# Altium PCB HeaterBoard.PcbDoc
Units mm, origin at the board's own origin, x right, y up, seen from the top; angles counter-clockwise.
Board outline 93.5 x 57 mm, 2 copper layers (Top Layer, Bottom Layer), stack 1.586 mm thick; 92 components, 36 nets, 205 pads, 73 vias.
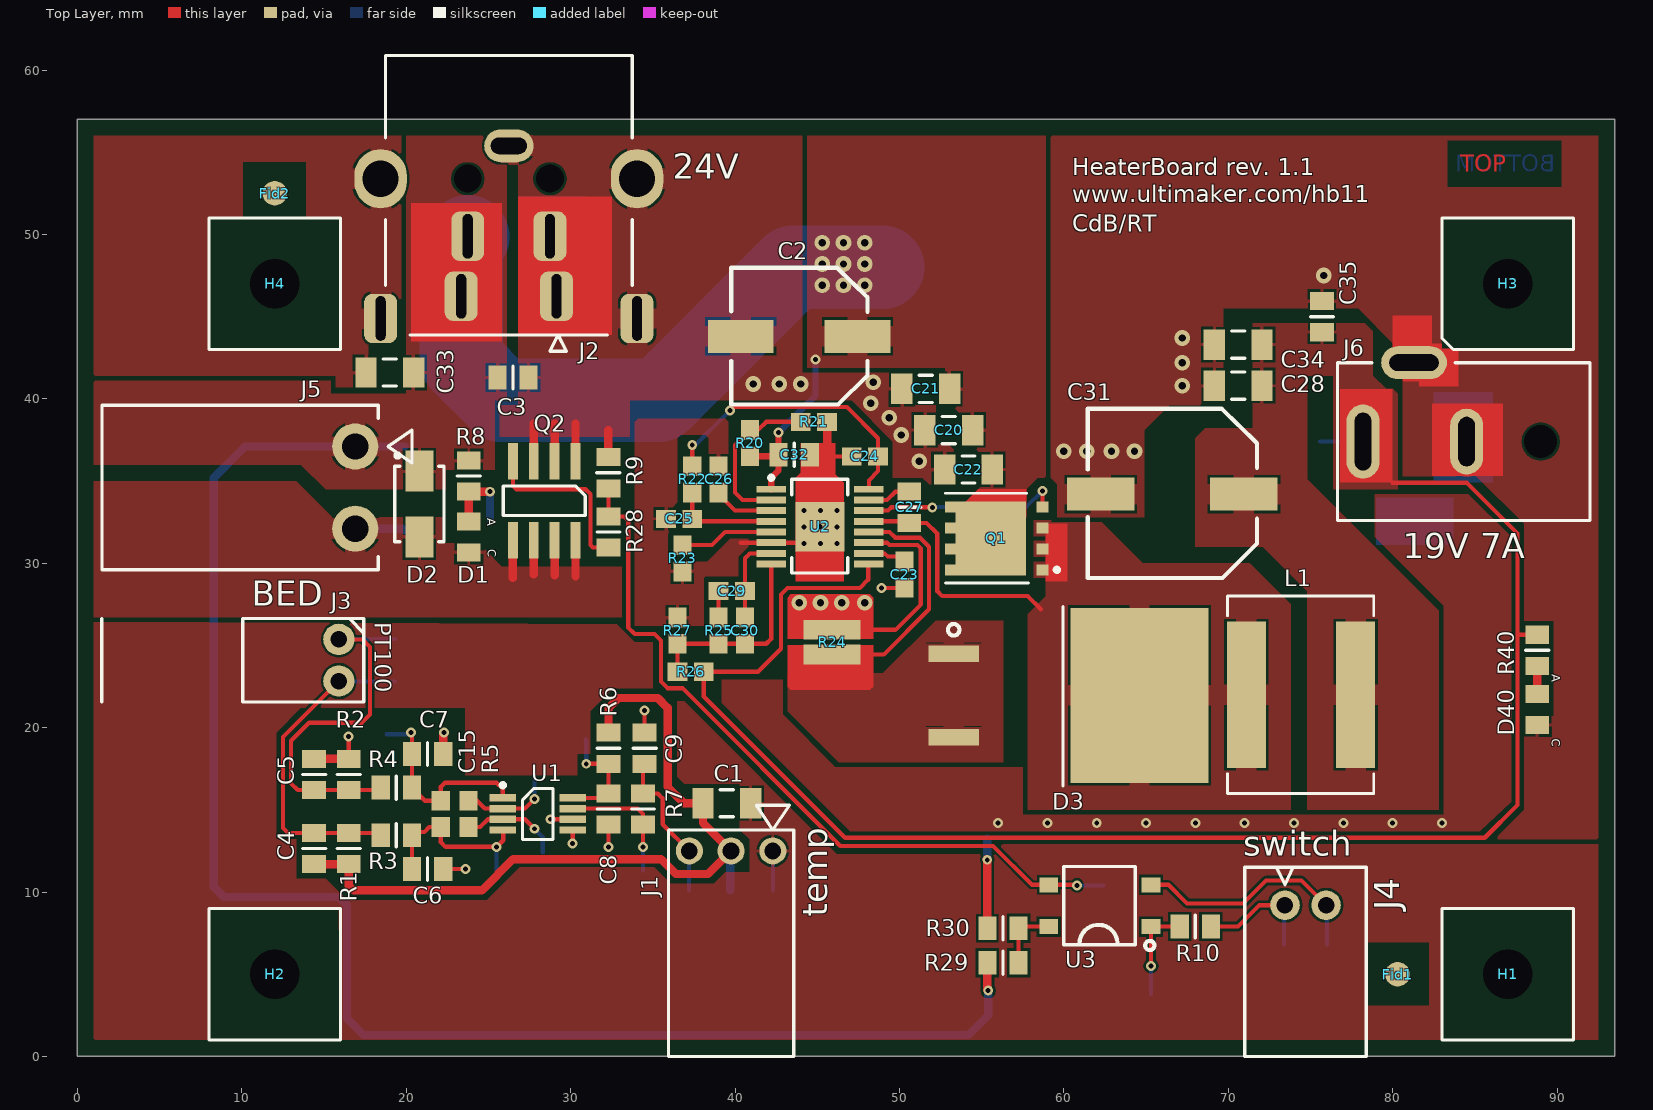
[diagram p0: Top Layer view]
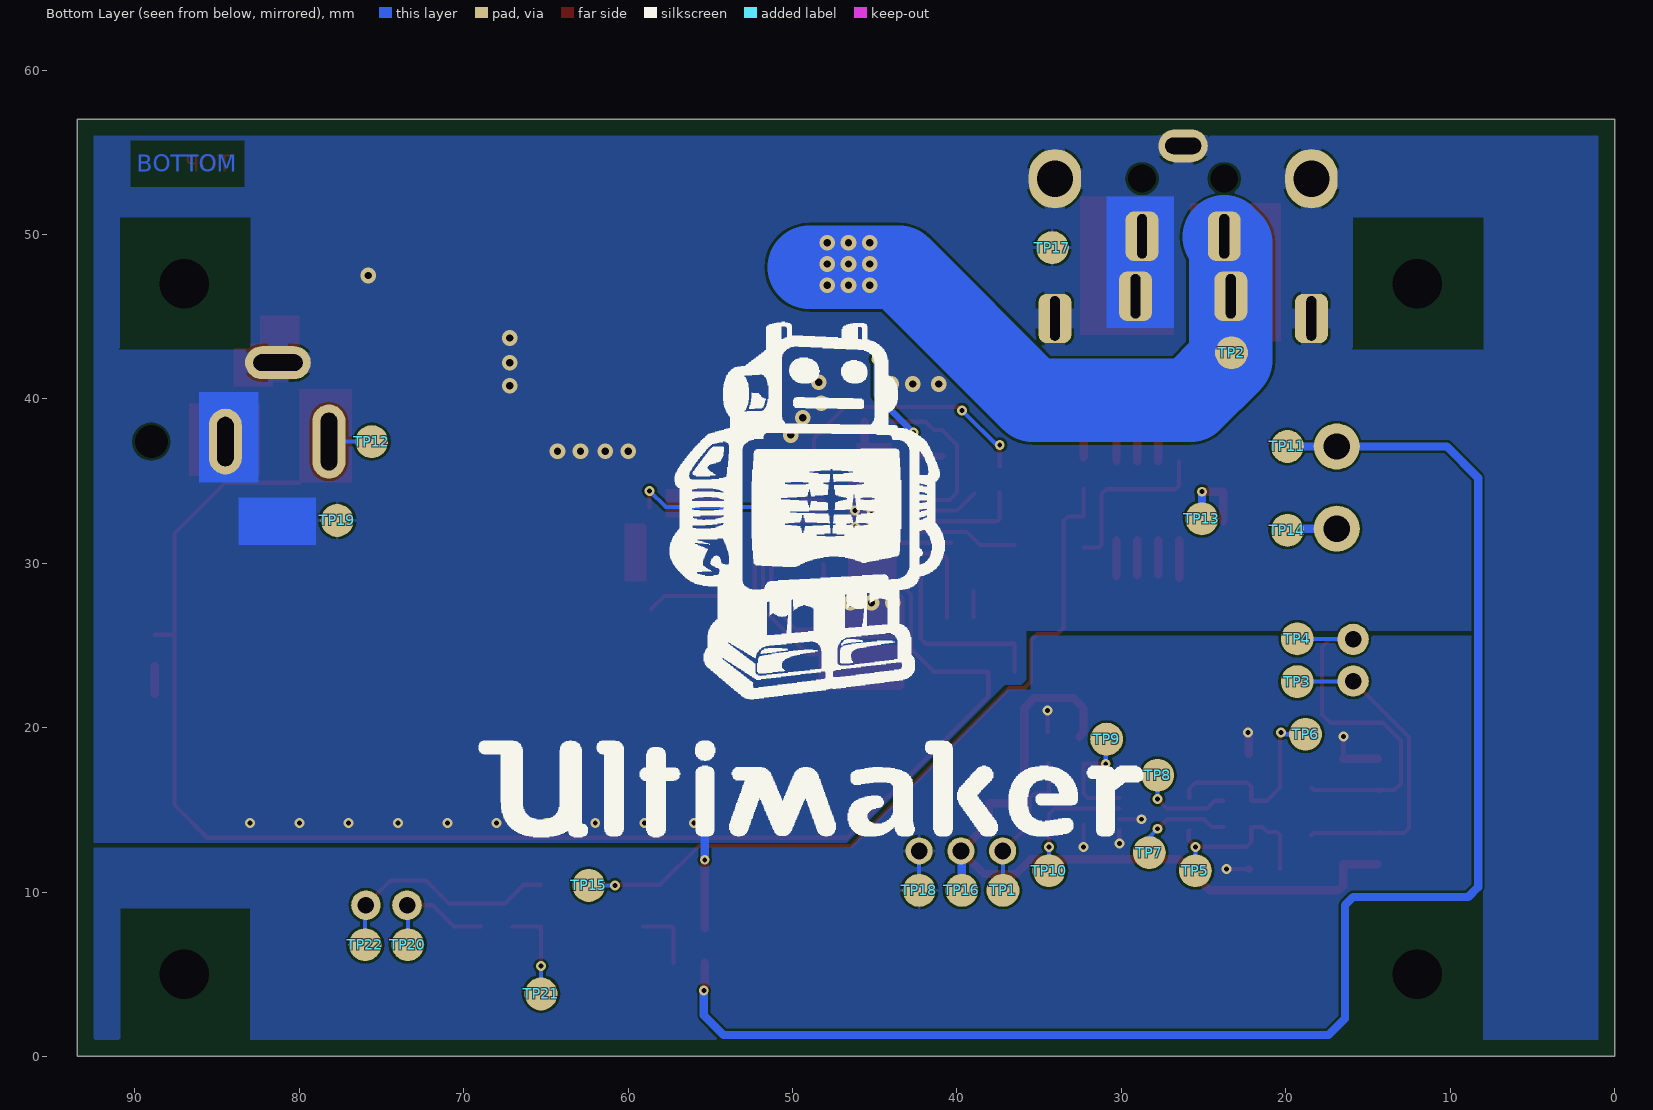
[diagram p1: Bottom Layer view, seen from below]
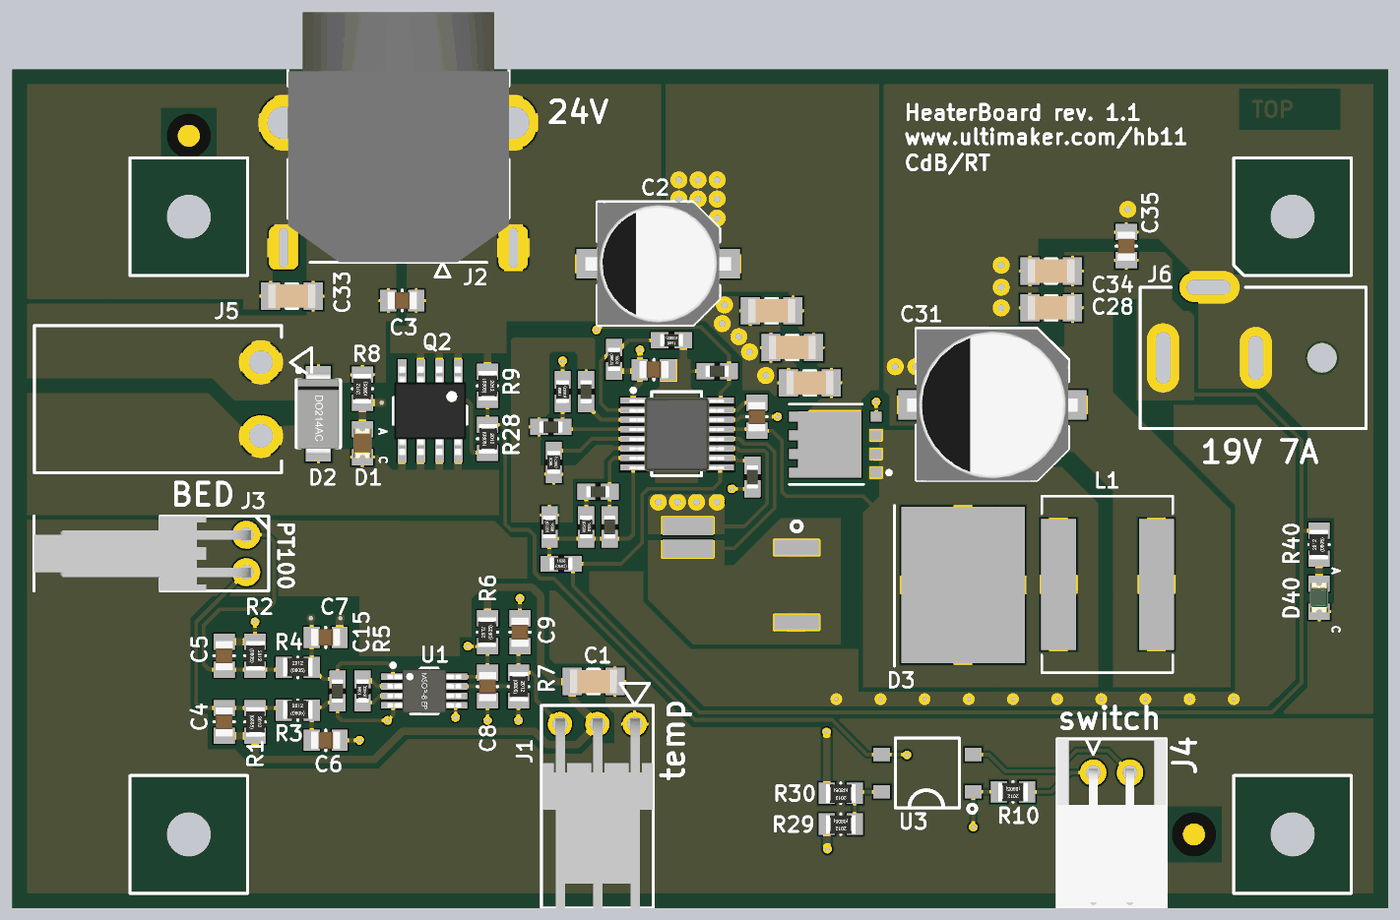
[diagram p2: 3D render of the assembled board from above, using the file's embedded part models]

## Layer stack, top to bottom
Top Layer: signal copper 0.018
Dielectric: core 1.55, FR-4, Dk 4.8
Bottom Layer: signal copper 0.018

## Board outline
0,0 0,57 93.5,57 93.5,0

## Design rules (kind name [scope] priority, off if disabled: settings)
Clearance Clearance-xPP-xTP-xTT [All] p1: gap=0.15
ComponentClearance [All] p1: gap=0.25 collisioncheckmode=3 verticalgap=0.25 showdistances=FALSE
DiffPairsRouting [All] p1: maxlimit=0.25 minlimit=0.25 mostfreqgap=0.25 maxuncoupledlength=12.5
Height [All] p1: minheight=0 maxheight=25 prefheight=12.5
HoleSize HoleSize-PTH [All] p1: absolutevalues=TRUE maxlimit=4 minlimit=0.25 maxpercent=80.000 minpercent=20.000
HoleToHoleClearance [All] p1: gap=0.15 allowstackedmicrovias=TRUE
MinimumAnnularRing "Minimum IAR  >0.45mm" [((ObjectKind = 'Pad') OR (ObjectKind = 'Via')) And (Layer = 'MultiLayer') And (HoleDiameter > AsMM(0.45))] p1: minimumring=0.15 // minimum inner annular ring for pads > 0.45mm finished hole size
MinimumAnnularRing "Minimum IAR <=0.45mm" [((ObjectKind = 'Pad') OR (ObjectKind = 'Via')) And (Layer = 'MultiLayer') And (HoleDiameter <= AsMM(0.45))] p2: minimumring=0.15 // minimum inner annular ring for pads <= 0.45mm finished hole size
MinimumSolderMaskSliver [All] p1: minsoldermaskwidth=0.1
PlaneClearance PlaneClearance-IPI [All] p1: clearance=0.4
PlaneConnect [All] p1: planeconnectstyle=Relief reliefexpansion=0.4 reliefentries=4 reliefconductorwidth=0.2 reliefairgap=0.2
PolygonConnect "PolygonConnect 50mill" [(InComponent('J2'))or (InComponent('C2'))or (InComponent('Q1'))or (InComponent('L1'))or (InComponent('R24'))     or (InComponent('C31'))  or (InComponent('J6'))or (InComponent('D3'))  or (InComponent('J5'))] p1: connectstyle=Relief reliefconductorwidth=1.27 reliefentries=4 polygonreliefangle="90 Angle"
PolygonConnect "PolygonConnect via" [IsVia] p2: connectstyle=Direct reliefconductorwidth=0.254 reliefentries=4 polygonreliefangle="90 Angle"
PolygonConnect PolygonConnect-xTW [All] p3: connectstyle=Relief reliefconductorwidth=0.2 reliefentries=4 polygonreliefangle="90 Angle"
RoomDefinition HeaterBoard [InComponentClass('HeaterBoard')] p1 off: confinementstyle=ConfineIn formatcopy=TRUE lockcomponents=FALSE outline 94.5,-8 107,-8 107,-3.7 94.5,-3.7
RoutingCorners [All] p1: cornerstyle=45-Degree minsetback=2.5 maxsetback=2.5
RoutingVias "RoutingVias > 0.45mm" [(ObjectKind = 'Via') And (HoleDiameter > AsMM(0.45))] p1: holewidth=0.5 width=1 viastyle="Through Hole" minholewidth=0.45 minwidth=0.95 maxholewidth=0.9 maxwidth=1.4 // finishet hole size > 0.45mm
RoutingVias "RoutingVias <= 0.45mm" [(ObjectKind = 'Via') And (HoleDiameter <= AsMM(0.45))] p2: holewidth=0.3 width=0.8 viastyle="Through Hole" minholewidth=0.25 minwidth=0.7 maxholewidth=0.5 maxwidth=1 // finishet hole size <= 0.45mm
SilkToSilkClearance [All] p1: silktosilkclearance=0.2
SilkscreenOverComponentPads [All] p1: minsilkscreentomaskgap=0.2
SolderMaskExpansion [All] p1: expansion=0.1
Width Width-xTW [All] p1: maxlimit=6.35 minlimit=0.15 preferedwidth=0.2 minimp=50.000000 maximp=50.000000 favimp=50.000000
17 further rules are at their usual default settings.

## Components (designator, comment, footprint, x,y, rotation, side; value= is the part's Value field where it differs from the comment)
C1 "10uF" "C1206 (3216)" 39.5,15.4 r180 top
C2 "150uF/35V" "ELCO Case F" 43.9,43.8 r0 top
C3 "100nF" "C0805 (2012)" 26.5,41.3 r0 top
C4 "100nF" "C0805 (2012)" 14.4,12.65 r90 top
C5 "100nF" "C0805 (2012)" 14.4,17.15 r90 top
C6 "100nF" "C0805 (2012)" 21.3,11.4 r180 top
C7 "100nF" "C0805 (2012)" 21.3,18.4 r0 top
C8 "100nF" "C0805 (2012)" 32.3,15.05 r270 top
C9 "10nF" "C0805 (2012)" 34.5,18.75 r270 top
C15 "1uF" "C0603 (1608)" 22.1,14.75 r270 top
C20 "4.7uF" "C1206 (3216)" 53,38.1 r0 top
C21 "4.7uF" "C1206 (3216)" 51.6,40.6 r0 top
C22 "4.7uF" "C1206 (3216)" 54.2,35.7 r0 top
C23 "2,2uF" "C0603 (1608)" 50.3,29.3 r90 top
C24 "680nF" "C0603 (1608)" 47.9,36.5 r0 top
C25 "680pF" "C0603 (1608)" 36.6,32.7 r0 top
C26 "10nF" "C0603 (1608)" 39,35.1 r270 top
C27 "33nF" "C0805 (2012)" 50.6,33.4 r90 top
C28 "4.7uF" "C1206 (3216)" 70.6,40.8 r0 top
C29 "1.5nF" "C0603 (1608)" 39.8,28.3 r180 top
C30 "100pF" "C0603 (1608)" 40.6,25.9 r270 top
C31 "330uF/35v" "ELCO CASE G" 66.6,34.2 r0 top
C32 "100nF" "C0805 (2012)" 43.6,36.6 r0 top
C33 "4.7uF" "C1206 (3216)" 19,41.6 r0 top
C34 "4.7uF" "C1206 (3216)" 70.6,43.3 r0 top
C35 "100nF" "C0805 (2012)" 75.7,45 r90 top
D1 "Red" LED0805-RED 23.8,31.6 r270 top
D2 "S1G" "DIODE DO214AC (SMA)" 20.8,33.6 r90 top
D3 "Diode Dual Schottky MBRB1545 45V 15A" "DIODE D2PAK(Case 418B)" 53.3,24.5 r180 top
D40 "Green" LED0805-GREEN 88.8,21.1 r270 top
Fid1 "Fiducial" "Fiducial 1,5mm" 80.3,5 r0 top
Fid2 "Fiducial" "Fiducial 1,5mm" 12,52.5 r90 top
H1 "3mm" "Mounting Hole 3mm NPTH" 87,5 r0 top
H2 "3mm" "Mounting Hole 3mm NPTH" 12,5 r0 top
H3 "3mm" "Mounting Hole 3mm NPTH" 87,47 r0 top
H4 "3mm" "Mounting Hole 3mm NPTH" 12,47 r0 top
J1 "22-05-3031" "HEADER 3P RIGHT ANGLE" 42.3,12.5 r180 top
J2 "KPJX-4S-S" "Con KPJX-4S-S" 26.242,53.388 r0 top
J3 "22-05-7028" "HEADER 2P RIGHT ANGLE" 15.9,24.1 r270 top
J4 "S2B-XH-A (LF)(SN)" "CON S2B-XH-A (LF)(SN)" 74.7,9.2 r0 top
J5 "2092-1372" "Con 2092-1372" 16.9,37.1 r270 top
J6 "487-836" "CON DC POWER SOCKET" 78.2,37.4 r180 top
L1 "10uH" "Inductor XAL1010-103MEB" 71.1,22 r0 top
Q1 "CSD18501Q5A" "IC SON5X6" 58.7,29.6 r0 top
Q2 "IRF8736PBF" "IC SOIC-8" 28.395,33.8 r270 top (schematic designator Q?)
R1 "2.2K" "R0805 (2012)" 16.5,12.65 r270 top
R2 "2.2K" "R0805 (2012)" 16.5,17.15 r270 top
R3 "10K" "R0805 (2012)" 19.4,13.45 r0 top
R4 "10K" "R0805 (2012)" 19.4,16.35 r0 top
R5 "5.49K" "R0603 (1608)" 23.8,14.75 r90 top
R6 "100E" "R0805 (2012)" 32.3,18.75 r90 top
R7 "100E" "R0805 (2012)" 34.4,15.05 r270 top
R8 "2.2K" "R0805 (2012)" 23.8,35.3 r90 top
R9 "1K" "R0805 (2012)" 32.295,35.5 r270 top
R10 "2.2K" "R0805 (2012)" 68,7.9 r180 top (schematic designator R?)
R20 "49.9K" "R0603 (1608)" 40.9,37.3 r270 top
R21 "3.48K" "R0603 (1608)" 44.8,38.6 r180 top
R22 "97.6K" "R0603 (1608)" 37.4,35.1 r90 top
R23 "28K" "R0603 (1608)" 36.8,30.3 r90 top
R24 "0E007" R1632X06N 45.9,25.2 r270 top
R25 "90.9K" "R0603 (1608)" 39,25.9 r270 top
R26 "28K" "R0603 (1608)" 37.3,23.4 r0 top
R27 "1.91K" "R0603 (1608)" 36.5,25.9 r270 top
R28 "100E" "R0805 (2012)" 32.3,31.9 r270 top
R29 "1K" "R0805 (2012)" 56.3,5.7 r180 top
R30 "1K" "R0805 (2012)" 56.3,7.8 r180 top
R40 "2.2K" "R0805 (2012)" 88.8,24.7 r90 top
TP1 "2mm" "TESTPOINT 2mm" 37.2,10.1 r90 bottom
TP2 "2mm" "TESTPOINT 2mm" 23.3,42.8 r270 bottom
TP3 "2mm" "TESTPOINT 2mm" 19.3,22.8 r270 bottom
TP4 "2mm" "TESTPOINT 2mm" 19.3,25.4 r270 bottom
TP5 "2mm" "TESTPOINT 2mm" 25.5,11.3 r270 bottom
TP6 "2mm" "TESTPOINT 2mm" 18.8,19.6 r270 bottom
TP7 "2mm" "TESTPOINT 2mm" 28.3,12.4 r270 bottom
TP8 "2mm" "TESTPOINT 2mm" 27.8,17.1 r270 bottom
TP9 "2mm" "TESTPOINT 2mm" 30.9,19.3 r270 bottom
TP10 "2mm" "TESTPOINT 2mm" 34.4,11.3 r270 bottom
TP11 "2mm" "TESTPOINT 2mm" 19.9,37.1 r270 bottom
TP12 "2mm" "TESTPOINT 2mm" 75.6,37.4 r270 bottom
TP13 "2mm" "TESTPOINT 2mm" 25.1,32.7 r270 bottom
TP14 "2mm" "TESTPOINT 2mm" 19.9,32 r270 bottom
TP15 "2mm" "TESTPOINT 2mm" 62.4,10.4 r270 bottom
TP16 "2mm" "TESTPOINT 2mm" 39.7,10.1 r180 bottom
TP17 "2mm" "TESTPOINT 2mm" 34.2,49.2 r270 bottom
TP18 "2mm" "TESTPOINT 2mm" 42.3,10.1 r270 bottom
TP19 "2mm" "TESTPOINT 2mm" 77.7,32.6 r270 bottom
TP20 "2mm" "TESTPOINT 2mm" 73.4,6.8 r0 bottom
TP21 "2mm" "TESTPOINT 2mm" 65.3,3.8 r0 bottom
TP22 "2mm" "TESTPOINT 2mm" 76,6.8 r0 bottom
U1 "INA826" "IC MSOP8" 28,14.75 r0 top
U2 "LM25088MH-1" "IC HTSSOP-16" 42.2,34.5 r0 top
U3 "SFH690BT" "IC SOP-4" 65.3,7.9 r180 top

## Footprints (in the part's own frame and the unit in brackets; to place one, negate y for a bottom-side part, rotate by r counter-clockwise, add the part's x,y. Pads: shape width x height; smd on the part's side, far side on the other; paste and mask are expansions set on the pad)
"C0603 (1608)" [mm] "Chip Capacitor, 2-Leads, Body 1.6x0.8mm, IPC Medium Density"
  rect 1.2x1.1 smd: 1(-0.8,0) 2(0.8,0)
  body extent -0.8,-0.4 0.8,0.4, height 0.9
"C0805 (2012)" [mm] "hip Capacitor, 2-Leads, Body 2,0x1.25mm, IPC Medium Density"
  rect 1.1x1.45 smd: 1(-0.95,0) 2(0.95,0)
  silkscreen extent 0,-0.7 0,0.7, body extent -1,-0.6 1,0.6, height 1.19
"C1206 (3216)" [mm] "Chip Capacitor, 2-Leads, Body 3.2x1.6mm, IPC Medium Density"
  rect 1.3x1.85 smd: 1(-1.45,0) 2(1.45,0)
  silkscreen extent -0.4,-0.82 0.4,0.82, body extent -1.6,-0.8 1.6,0.8, height 0.77
"Con 2092-1372" [mm] "Connector 2092-1372 2p therm Block r.a."
  round 2.8 hole 1.6: 1(0,0) 2(5,0)
  silkscreen extent -2.5,-15.4 7.5,3.45, body extent -2.5,-15.4 7.5,1.4, height 13.4
"CON DC POWER SOCKET" [mm]
  round 0 hole 2: 0(-10.8,0)
  oval 2x4.5 hole 1 slot 3.5 at 90 deg: 1(0,0)
  oval 2x4 hole 1 slot 3 at 90 deg: 2(-6.3,0)
  oval 4x2 hole 1 slot 3 at 0 deg: 3(-3.1,-4.8)
  silkscreen extent -13.8,-4.8 1.55,4.8
"Con KPJX-4S-S" [mm]
  round 0 hole 1.7 unplated: 0(-2.5,0) 0(2.5,0)
  rrect50% 2x3 hole 0.6 slot 2.7 at 90 deg: 1(2.9,-7.15) 2(-2.9,-7.15) 3(2.5,-3.5) 4(-2.5,-3.5) 5(-7.8,-8.5) 5(7.8,-8.5)
  oval 3.2x3.6 hole 2.2: 5(-7.8,0) 5(7.8,0)
  oval 3x2 hole 1 slot 2.2 at 0 deg: 5(0,2)
  silkscreen extent -7.5,-10.5 7.5,7.5, body extent -7.5,-9.5 7.5,7.5, height 15
"CON S2B-XH-A (LF)(SN)" [mm]
  round 1.8 hole 1: 1(-1.25,0) 2(1.25,0)
  silkscreen extent -3.7,-9.2 3.7,2.3, body extent -3.7,-9.2 3.7,2.3, height 6.1
"DIODE D2PAK(Case 418B)" [mm]
  rect 3.05x1.016 smd: 1(0,0) 3(0,5.08)
  rect 8.38x10.66 smd: 4(-11.305,2.54)
  silkscreen extent -6.65,-2.85 0.35,8.05
"DIODE DO214AC (SMA)" [mm] "Molded Diode, 2-Leads, Body 4.3x2.6mm, IPC Medium Density"
  rect 2.5x1.7 smd: 1(-2,0) 2(2,0)
  silkscreen extent -2.3,-1.5 3.07,1.5, body extent -2.74,-1.4 2.74,1.4, height 2.3
"ELCO Case F" [mm] "Panasonic Elco 8x10,5mm (dxh)"
  rect 4x2 smd: 1(3.55,0) 2(-3.55,0)
  silkscreen extent -4.13,-4.15 4.15,4.18, body extent -4.95,-4.15 4.95,4.15, height 10.21
"ELCO CASE G" [mm] "Panasonic Elco 10x10,5mm (dxh)"
  rect 4.1x2 smd: 1(4.35,0) 2(-4.35,0)
  silkscreen extent -5.15,-5.1 5.15,5.2, body extent -5.8,-5.15 5.8,5.15, height 10.21
"Fiducial 1,5mm" [mm] "Fiducial 1,5mm"
  round 1.5 smd paste-3 mask+0.75: ""(0,0)
"HEADER 2P RIGHT ANGLE" [mm]
  round 1.9 hole 1: 1(-1.27,0) 2(1.27,0)
  silkscreen extent -2.54,-14.42 2.54,1.52, body extent -2.54,-14.42 2.54,0.32, height 5.87
"HEADER 3P RIGHT ANGLE" [mm]
  round 1.65 hole 1.02: 1(0,0) 2(2.54,0) 3(5.08,0)
  silkscreen extent -1.27,-2.77 6.35,12.5, body extent -1.23,-0.4 6.23,12.53, height 6.38
"IC HTSSOP-16" [mm] "PWP0016A"
  rect 3x3 smd: 0(2.97,-2.275)
  rect 1.78x0.42 smd: 1(0,0) 2(0,-0.65) 3(0,-1.3) 4(0,-1.95) 5(0,-2.6) 6(0,-3.25) 7(0,-3.9) 8(0,-4.55) 9(5.94,-4.55) 10(5.94,-3.9) 11(5.94,-3.25) 12(5.94,-2.6) 13(5.94,-1.95) 14(5.94,-1.3) 15(5.94,-0.65) 16(5.94,0)
  silkscreen extent -0.12,-5.1 4.65,0.82, body extent -0.25,-4.8 6.17,0.2, height 0.99
"IC MSOP8" [mm] "TSOP, 8-Leads, Body 3.1x3.1mm (max), Pitch 0.65mm, IPC Medium Density"
  rect 1.6x0.45 smd: 1(-2.125,0.975) 2(-2.125,0.325) 3(-2.125,-0.325) 4(-2.125,-0.975) 5(2.125,-0.975) 6(2.125,-0.325) 7(2.125,0.325) 8(2.125,0.975)
  silkscreen extent -2.25,-1.55 0.92,1.87, body extent -2.5,-1.5 2.5,1.5, height 1.09
"IC SOIC-8" [mm] "SOIC, 8-Leads, Body 5,0x4,0mm (max), Pitch 1,27mm, IPC Medium Density"
  rect 2.2x0.6 smd: 1(-2.4,1.905) 2(-2.4,0.635) 3(-2.4,-0.635) 4(-2.4,-1.905) 5(2.4,-1.905) 6(2.4,-0.635) 7(2.4,0.635) 8(2.4,1.905)
  silkscreen extent -0.9,-2.5 0.9,2.5, body extent -3,-2.45 3,2.45, height 1.75
"IC SON5X6" [mm] "IC SON5x6"
  rect 4.3x4.5 smd: 0(-3.15,1.905)
  rect 0.75x0.67 smd: 1(0,0) 2(0,1.27) 3(0,2.54) 4(0,3.81)
  rect 0.65x0.67 smd: 5(-5.6,3.81) 6(-5.6,2.54) 7(-5.6,1.27) 8(-5.6,0)
  silkscreen extent -5.9,-0.8 1,4.65
"IC SOP-4" [mm]
  rect 1.14x0.91 smd: 1(0,0) 2(0,-2.54) 3(6.22,-2.54) 4(6.22,0)
  silkscreen extent -0.21,-3.65 5.3,1.43
"Inductor XAL1010-103MEB" [mm] "Inductor XAL1010-103MEB"
  rect 2.38x8.91 smd paste+0: 1(0,0) 2(6.65,0)
  silkscreen extent -1.15,-6 7.75,6
LED0805-GREEN [mm]
  rect 1.1x1.45 smd: 1(-0.95,0) 2(0.95,0)
  body extent -1.01,-0.62 1.01,0.63, height 1.1
LED0805-RED [mm]
  rect 1.1x1.45 smd: 1(-0.95,0) 2(0.95,0)
  body extent -1.01,-0.62 1.01,0.63, height 1.1
"Mounting Hole 3mm NPTH" [mm] "Mounting Hole 3mm NPTH"
  round 0 hole 3 unplated: 0(0,0)
"R0603 (1608)" [mm] "hip Resistor, 2-Leads, Body 1.55x0.85mm, IPC Medium Density"
  rect 1.2x1.1 smd: 1(-0.8,0) 2(0.8,0)
  body extent -0.77,-0.42 0.78,0.43, height 0.45
"R0805 (2012)" [mm] "hip Resistor, 2-Leads, Body 2,0x1.25mm, IPC Medium Density"
  rect 1.1x1.45 smd: 1(-0.95,0) 2(0.95,0)
  silkscreen extent 0,-0.7 0,0.7, body extent -1,-0.6 1,0.65, height 0.44
R1632X06N [mm] "Chip Resistor, 2-Leads, Body 1.6x3.2mm, IPC Medium Density"
  rect 1.2x3.45 smd: 1(-0.75,0) 2(0.75,0)
  body extent -0.9,-1.7 0.9,1.7, height 0.6
"TESTPOINT 2mm" [mm] "TESTPOINT 2mm"
  round 2 smd paste-2 mask+0: 1(0,0)

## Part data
C1: library part "Cap 10uF X7R 1206", "Cap 10uF X7R 1206  10% 25V"
C2: "Cap elco 150uF 35V case F  EEHZA1 PAN"
C3 C4 C5 C6 C7 C8 C32 C35: library part "Cap 100nF X7R 0805", "Cap 100nF X7R 0805 10% 50V"
C9: library part "Cap 10nF X7R 0805", "Cap 10nF X7R 0805 10% 50V"
C15: library part "Cap 1uF X5R 0603", "Cap 1uF X5R 0603 10% 10V"
C20 C21 C22 C28 C33 C34: library part "Cap 4.7uF 50V X7R 1206", "Cap 4.7uF X7R 1206 10% 50V"
C23: library part "Cap 2,2uF X7R 0603", "Cap 2,2uF X7R 0603 10% 6,3V"
C24: library part "Cap 680nF X7R 0603", "Cap 680nF X7R 0603 10% 16V"
C25: library part "Cap 680pF X7R 0603", "Cap 680pF NPO 0603 5% 50V"
C26: library part "Cap 10nF X7R 0603", "Cap 10nF X7R 0603 10% 50V"
C27: library part "Cap 33nF X7R 0805", "Cap 33nF X7R 0805 10% 50V"
C29: library part "Cap 1.5nF X7R 0603", "Cap 1.5nF X7R 0603 5% 50V"
C30: library part "Cap 100pF X7R 0603", "Cap 100pF X7R 0603 5% 50V"
C31: "Cap elco 330uF 35V case G UD Nichicon"
D1: "LED ROOD HSMH-C170 0805 AVAGO"
D2: library part "Diode S1G", "Diode S1G DO-214AC 400V 1A"
D3: library part "Diode MBRB1545", "MBRB1545"
D40: "LED GROEN HSMG-C170 0805 AVAGO"
H1 H2 H3 H4: "Mounting Hole 3mm NPTH"
J1: "Header 3p right angle 22-05-3031 Molex"
J2: "Connector 5p KPJX-4S-S KYCON"
J3: "Header 2p right angle 22-05-7028 Molex"
J4: "Connector S2B-XH-A (LF)(SN)  2p r.a."
J5: "Connector 2092-1372 2p therm Block r.a."
J6: "DC Power Socket 2.5mm Right Angle PCB Mount"
L1: library part "Inductor 10uH SMD", "Inductor 10uH 11A SMD"
Q1: library part "MOSFET-N CSD18501Q5A", "MOSFET-N CSD18501Q5A 40V 100A"
Q2: "MOSFET-N IRF8736PBF 30V 18A"
R1 R2 R8 R10 R40: library part "Res 2.2K 0805", "Res 2.2K 0805 1% 100mW"
R3 R4: library part "Res 10K 0805", "Res 10K 0805 1% 100mW"
R5: library part "Res 5.49K 0603", "Res 5.49K 0603 1% 63mW"
R6 R7 R28: library part "Res 100E 0805", "Res 100E 0805 1% 125mW"
R9 R29 R30: library part "Res 1K 0805", "Res 1K 0805 1% 100mW"
R20: library part "Res 49.9K 0603", "Res 49.9K 0603 1% 63mW"
R21: library part "Res 3.48K 0603", "Res 3.48K 0603 1% 63mW"
R22: library part "Res 97.6K 0603", "Res 97.6K 0603 1% 63mW"
R23 R26: library part "Res 28K 0603", "Res 28K 0603 1% 63mW"
R24: library part "Res 0E007 1632", "Res 0E007 1632 1% 1W"
R25: library part "Res 90.9K 0603", "Res 90.9K 0603 1% 63mW"
R27: library part "Res 1.91K 0603", "Res 1.91K 0603 1% 63mW"
TP1 TP2 TP3 TP4 TP5 TP6 TP7 TP8 TP9 TP10 TP11 TP12 TP13 TP14 TP15 TP16 TP17 TP18 TP19 TP20 TP21 TP22: "Testpoint, 2mm, round"
U1: library part "IC INA826", "IC OP AMP, instr, 1MHz"
U2: library part "IC LM25088MH-1", "IC DC-DC Buck Controller"
U3: library part "Opto SFH690BT", "Opto SFH690BT SOP-4"

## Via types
v1: diameter 0.6, hole 0.3, Top Layer to Bottom Layer, tented bottom, 40 vias
v2: diameter 0.95, hole 0.45, Top Layer to Bottom Layer, 29 vias
v3: diameter 0.6, hole 0.3, Top Layer to Bottom Layer, tented both sides, 4 vias

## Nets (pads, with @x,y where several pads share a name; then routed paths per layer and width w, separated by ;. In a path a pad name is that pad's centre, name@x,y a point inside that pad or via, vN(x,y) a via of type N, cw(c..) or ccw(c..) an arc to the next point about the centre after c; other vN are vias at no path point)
+5V: C1.2 C4.1 J1.2 R1.2 R6.2 TP16.1 | length 47.9
  Top Layer w0.508: C4.1 R1.2 16.5,10.4 16.8,10.1 24.6,10.1 26.5,12 35.5,12 36.4,11.1 38.36,11.1 J1.2 38.05,14.21 C1.2 36.9,15.4 35.9,16.4 35.9,21.2 35.3,21.8 32.9,21.8 32.3,21.2 R6.2 R6.2@32.55,19.45
  Bottom Layer w0.508: TP16.1 39.7,12.44 J1.2
+19V: C28.2 C31.1 C34.2 C35.1 J6.1 L1.2 R26.2 R40.2 TP12.1 U2.9 | length 99.7
  Top Layer w0.254: U2.9 48.1,29.91 48.1,29 47.6,28.5 43.2,28.5 42.8,28.1 42.8,24.8 41.4,23.4 R26.2 38.1,21.9 46.7,13.3 85.6,13.3 87.6,15.3 87.6,31.8 84.5,34.9 80,34.9 ; 87.65,25.65 R40.2
  Bottom Layer w0.254: TP12.1 J6.1
+24V: C2.1 C3.1 C20.2 C21.2 C22.2 C32.1 C33.2 D2.2 J2.2 J2.4 J5.1 Q1.0 Q1.5 Q1.6 Q1.7 Q1.8 R8.2 R20.2 R29.2 TP2.1 TP11.1 U2.1 | length 147
  Top Layer w0.381: R20.2 42.55,36.5 C32.1 ; U2.1 42.2,35.2 42.65,35.65 C32.1 ; v1(42.65,37.95) C32.1
  Top Layer w0.508: R29.2 55.35,4.05 v1(55.4,4)
  Bottom Layer w0.381: TP2.1@23.342,42.35 TP2.1@23.4,42.292 ; v1(42.65,37.95) 44.9,40.2 v1(44.9,42.4)
  Bottom Layer w0.508: TP11.1 J5.1 10.2,37.1 8.3,35.2 8.3,10.3 8.9,9.7 15.9,9.7 16.4,9.2 16.4,2.3 17.4,1.3 54.2,1.3 55.4,2.5 v1(55.4,4) ; 24.8,38.4 27.3,38.4
  Bottom Layer w5.08: J2.4@23.742,49.848 23.342,49.448 J2.2 23.342,42.35 25.792,39.9 35.4,39.9 43.5,48 49,48
  other v2: 45.3,46.9 46.6,46.9 47.9,46.9 45.3,48.2 46.6,48.2 47.9,48.2 45.3,49.5 46.6,49.5 47.9,49.5
GND: C2.2 C3.2 C20.1 C21.1 C22.1 C23.1 C24.1 C25.1 C26.1 C28.1 C31.2 C32.2 C33.1 C34.1 C35.2 D40.2 J2.1 J2.3 J2.5 J6.2 J6.3 Q2.1 Q2.2 Q2.3 R9.1 R21.1 R23.1 R24.1 R27.1 R30.2 TP17.1 TP19.1 U2.0 U2.6 U2.11 | length 37.2
  Top Layer w0.254: 40.35,31.25 U2.6 44.195,31.25 v1(45.17,32.225) ; 45.3,36.5 C24.1 ; R24.1 49.75,25.95 51.3,27.5 51.3,30.9 51.1,31.1 49.4,31.1 49.25,31.25 U2.11 ; v1(48.9,28.5) C23.1
  Top Layer w0.508: Q2.3 27.76,38.495 ; Q2.2 29.03,38.495 ; Q2.1 30.3,38.495 ; R9.1 32.295,38.095 ; 45.6,36.9 R21.1 ; v1@55.3,12 v1(55.34,11.96) 55.35,11.95 R30.2
  Bottom Layer w0.508: J2.1@28.542,45.8 J2.1@28.742,46 ; v1(55.34,11.96) 55.34,13.24
  other v1: 56,14.2 59,14.2 62,14.2 65,14.2 68,14.2 71,14.2 74,14.2 77,14.2 80,14.2 83,14.2 44.2,31.2 45.2,31.2 46.2,31.2 44.2,32.2 46.2,32.2 44.2,33.2 45.2,33.2 46.2,33.2
  other v2: 43.9,27.6 45.2,27.6 46.5,27.6 47.9,27.6 51.2,36.2 60,36.8 61.4,36.8 62.9,36.8 64.3,36.8 50.1,37.8 49.37,38.84 48.25,39.73 67.2,40.8 41.1,40.9 42.7,40.9 44,40.9 48.4,41 67.2,42.2 67.2,43.7 75.8,47.5
GND2: C1.1 C5.2 C6.1 C7.2 C8.2 C9.1 J1.1 R2.1 TP18.1 U1.5 U1.6 | length 13.4
  Top Layer w0.254: R2.1 v1(16.5,19.45) ; C6.1 v1(23.6,11.4) ; v3(28.775,14.425) U1.6 ; v1(30.125,12.95) U1.5 ; v1(32.3,12.75) C8.2 ; C9.1 v1(34.5,21.05)
  Top Layer w0.508: C5.2 R2.1 ; C7.2 22.25,19.65 v3(22.3,19.7)
  Bottom Layer w0.254: TP18.1 J1.1
NetC4_2: C4.2 J3.2 R1.1 R3.1 TP3.1 | length 20
  Top Layer w0.254: C4.2@14.31,13.65 14.38,13.58 C4.2 ; J3.2 12.5,19.43 12.5,13.9 12.8,13.6 C4.2 ; R3.1 18.3,13.6 R1.1 C4.2
  Bottom Layer w0.254: J3.2@15.93,22.8 TP3.1
NetC5_1: C5.1 J3.1 R2.2 R4.1 TP4.1 | length 23.6
  Top Layer w0.254: C5.1@14.19,16.25 14.32,16.12 C5.1 ; J3.1 17.33,25.37 17.8,24.9 17.8,20.8 17.3,20.3 14.1,20.3 13,19.2 13,16.6 13.4,16.2 C5.1 ; R4.1 18.3,16.2 R2.2 C5.1
  Bottom Layer w0.254: J3.1@15.93,25.4 TP4.1
NetC6_2: C6.2 C15.2 R3.2 TP5.1 U1.4 | length 11.1
  Top Layer w0.254: C6.2 20.35,13.35 20.3,13.4 R3.2 20.55,13.65 21.1,13.65 21.4,13.95 C15.2 22.1,13.05 22.4,12.75 v1(25.5,12.75) 25.9,13.15 25.9,13.75 U1.4
  Bottom Layer w0.254: TP5.1 v1(25.5,12.75)
NetC7_1: C7.1 C15.1 R4.2 TP6.1 U1.1 | length 12.4
  Top Layer w0.254: v3@20.35,19.65 C7.1 R4.2 21.15,15.55 C15.1 22.1,16.4 22.35,16.65 25.5,16.65 25.875,16.275 U1.1
  Bottom Layer w0.254: TP6.1 20.2,19.6 v3(20.3,19.7)
NetC8_1: C8.1 R6.1 TP9.1 U1.8 | length 7
  Top Layer w0.254: U1.8 32.025,15.725 C8.1 R6.1 v1(30.95,17.8)
  Bottom Layer w0.254: TP9.1 30.95,19.25 v1(30.95,17.8)
NetC23_2: C23.2 U2.10 | length 2.4
  Top Layer w0.254: U2.10 49.1,30.6 49.3,30.4 50,30.4 C23.2
NetC24_2: C24.2 R22.2 U2.16 | length 18
  Top Layer w0.254: R22.2 v1(37.4,37.2) ; v1(39.7,39.3) 39.9,39.5 46.8,39.5 48.7,37.6 C24.2 48.7,35.6 48.14,35.04 U2.16
  Bottom Layer w0.254: v1(37.4,37.2) 37.4,37 v1(39.7,39.3)
NetC25_2: C25.2 R22.1 U2.4 | length 6.5
  Top Layer w0.254: R22.1 C25.2 37.55,32.55 U2.4
NetC26_2: C26.2 U2.3 | length 3.7
  Top Layer w0.254: C26.2@38.95,34.25 40,33.2 U2.3
NetC27_1: C27.1 D3.4 L1.1 Q1.1 Q1.2 Q1.3 U2.13 | length 14.7
  Top Layer w0.254: U2.13 50.5,32.55 C27.1 51.65,32.45 52.3,31.8 52.3,28.3 52.6,28 57.8,28 58.6,27.2
NetC27_2: C27.2 U2.15 | length 2.7
  Top Layer w0.254: U2.15 49.25,33.85 49.75,34.35 C27.2
NetC29_1: C29.1 C30.1 U2.7 | length 5.3
  Top Layer w0.254: C30.1 C29.1 40.6,30.3 40.9,30.6 U2.7
NetC29_2: C29.2 R25.1 | length 1.6
  Top Layer w0.254: R25.1 C29.2
NetC30_2: C30.2 R25.2 R26.1 R27.2 U2.8 | length 12.1
  Top Layer w0.254: R26.1 R27.2 R25.2 C30.2 41.9,25.1 42.2,25.4 U2.8
NetD1_1: D1.1 R8.1 TP13.1 | length 4.8
  Top Layer w0.508: D1.1 R8.1 v3(25.1,34.35)
  Bottom Layer w0.508: TP13.1 v3(25.1,34.35)
NetD1_2: D1.2 D2.1 J5.2 Q2.5 Q2.6 Q2.7 Q2.8 TP14.1 | length 11.7
  Top Layer w0.508: 26.49,29.105 Q2.5 ; 27.76,29.335 Q2.6 ; 29.03,29.265 Q2.7 ; 30.3,29.205 Q2.8
  Bottom Layer w0.508: J5.2 19.8,32.1 TP14.1
NetD3_1: D3.1 D3.3 R24.2 U2.12 | length 14.9
  Top Layer w0.254: R24.2 49.05,24.45 51.8,27.2 51.8,31 51.25,31.55 49.75,31.55 49.4,31.9 U2.12
NetD40_1: D40.1 R40.1 | length 1.7
  Top Layer w0.508: D40.1 R40.1
NetJ4_1: J4.1 R10.1 TP20.1 | length 7.5
  Top Layer w0.254: R10.1 70.6,7.9 71.9,9.2 J4.1
  Bottom Layer w0.254: TP20.1 73.4,9.15 J4.1
NetJ4_2: J4.2 TP22.1 U3.2 | length 14.7
  Top Layer w0.254: U3.2 66.36,10.44 67.5,9.3 70.9,9.3 72.3,10.7 74.45,10.7 J4.2
  Bottom Layer w0.254: J4.2 76,9.15 TP22.1
NetQ1_4: Q1.4 U2.14 | length 12
  Top Layer w0.254: U2.14 49.3,33.2 49.5,33.4 v1(52,33.4) ; Q1.4 v1(58.7,34.4)
  Bottom Layer w0.254: v1(52,33.4) 52.01,33.41 57.71,33.41 v1(58.7,34.4)
NetQ2_4: Q2.4 R28.2 | length 10.7
  Top Layer w0.254: Q2.4 26.49,34.71 26.7,34.5 30.9,34.5 31.2,34.2 31.2,31.1 31.35,30.95 R28.2
NetR5_1: R5.1 TP7.1 U1.3 | length 6.1
  Top Layer w0.254: R5.1 24.5,13.95 24.975,14.425 U1.3 27.225,14.425 v1(27.8,13.85)
  Bottom Layer w0.254: v1(27.8,13.85) 28.3,13.35 TP7.1
NetR5_2: R5.2 TP8.1 U1.2 | length 5.9
  Top Layer w0.254: R5.2 24.3,15.55 24.775,15.075 U1.2 27.225,15.075 v1(27.8,15.65)
  Bottom Layer w0.254: v1(27.8,15.65) TP8.1
NetR7_2: R7.2 TP10.1 U1.7 | length 7.9
  Top Layer w0.254: U1.7 34.075,15.075 34.4,14.75 R7.2 v1(34.4,12.75)
  Bottom Layer w0.254: TP10.1 v1(34.4,12.75)
NetR9_2: R9.2 R28.1 TP15.1 U3.3 | length 46.4
  Top Layer w0.254: R9.2 32.3,34.545 R28.1 33.25,32.85 33.5,32.6 33.5,26.1 33.9,25.7 35.1,25.7 35.5,25.3 35.5,22.8 35.9,22.4 36.8,22.4 46.4,12.8 55.7,12.8 58.06,10.44 U3.3 60.76,10.44 v1(60.8,10.4)
  Bottom Layer w0.254: v1(60.8,10.4) TP15.1
NetR10_2: R10.2 TP21.1 U3.1 | length 5.9
  Top Layer w0.254: v1(65.3,5.5) U3.1 R10.2
  Bottom Layer w0.254: TP21.1 v1(65.3,5.5)
NetR20_1: R20.1 R21.2 U2.2 | length 9.9
  Top Layer w0.254: U2.2 40.45,33.85 40,34.3 40,37.2 R20.1 41.4,38.1 41.9,38.6 R21.2
NetR23_2: R23.2 U2.5 | length 6
  Top Layer w0.254: R23.2@36.5,31.1 38.6,31.1 39.4,31.9 U2.5
NetR29_1: R29.1 R30.1 U3.4 | length 4
  Top Layer w0.254: R29.1 R30.1 57.35,7.9 U3.4
TEMP: C9.2 J1.3 R7.1 TP1.1 | length 9.5
  Top Layer w0.254: C9.2 34.45,17.85 34.4,17.8 R7.1 35.3,16 35.6,15.7 35.6,14.12 J1.3
  Bottom Layer w0.254: TP1.1 37.2,12.48 J1.3
pads on no net: Fid1. Fid2. H1.0 H2.0 H3.0 H4.0 J2.0 J6.0

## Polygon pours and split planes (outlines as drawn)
+19V on Top Layer "Top Layer-No Net 1" (solid, remove dead copper, pour order 1005): 74.8,15 74.8,28.3 72.1,31 68,31 68,37.6 68.6,38.2 71.5,38.2 71.5,44.6 78.3,44.6 78.8,44.1 78.8,41.4 79.6,40.6 80,40.6 80.3,40.3 80.3,34.5 76.4,34.5 76.4,41.4 74.8,41.4 74.8,37.7 74.8,35.1 82.8,27.1 82.8,15
GND on Top Layer "Top Layer-No Net 1" (solid, pour order 1002): 44.1,56 44.1,41.6 50.8,41.6 50.8,39.6 52.2,39.6 52.2,37.2 53,37.2 53.4,36.8 53.4,34.8 51.8,34.8 51.4,35.2 49.6,35.2 49.6,37.4 47.1,39.9 33.6,39.9 33.6,37.7 25.7,37.7 25.7,39.6 26.8,39.6 26.8,56
GND on Top Layer "Top Layer-No Net 1" (solid, pour order 1000): 38.3,30.1 39.7,31.5 40.8,31.5 40.8,31 40.2,30.4 40.2,29.2 38.2,29.2 38.1,29.1 38.1,26.2 33.9,26.2 33.9,38.6 34.1,38.8 39.4,38.8 39.6,38.6 39.6,35.3 38.4,35.3 38.4,37.6 38.2,37.8 36.7,37.8 36.5,37.6 36.5,33.7 36.2,33.4 36.2,32.1 35.9,31.8 35.9,30.1
NetC27_1 on Top Layer "Top Layer-No Net 1" (solid, pour order 1000): 58.9,28 57.8,26.9 57.8,15 73.8,15 73.8,27.5 71.3,30 64.8,30 62.3,32.5 58.8,32.5 58.9,32.3
NetD3_1 on Top Layer "Top Layer-No Net 1" (solid, pour order 1001): 43.2,22.5 43.2,21 46.3,17.9 56.3,17.9 56.3,26.5 52.2,26.5 49,23.3 43.2,23.3
GND on Top Layer "Top Layer-No Net 1" (solid, pour order 1004): 57.5,14.7 57.5,17.6 46.1,17.6 42.9,20.8 42.9,22.9 39.2,22.9 39.2,21.5 47,13.7 85.3,13.7 87.2,15.5 87.2,31.6 84.6,34.2 78.9,34.2 78.9,31.6 83.1,27.4 83.1,14.7
NetD1_2 on Top Layer "Top Layer-No Net 1" (solid, pour order 1001): 8,35 1,35 1,26.7 33.1,26.7 33.1,29.8 25.8,29.8 24.4,31.2 22.2,31.2 22.2,32.8 15.5,32.8 13.3,35
+24V on Top Layer "Top Layer-No Net 1" (solid, pour order 1002): 58.9,56 58.9,35.2 58.4,35.2 57.7,34.5 57.7,33 57.6,31.5 53.5,31.5 53.5,33.2 55,34.7 55,36.6 53.8,37.8 53.8,39 52.8,40 52.8,41.9 44.4,41.9 44.4,46.2 44.4,49.5 44.4,56 26.1,56 26.1,39.9 25.4,39.9 25.4,35.7 22.4,35.7 22.4,34.5 15.1,34.5 13.6,36 1,36 1,41.1 15.4,41.1 15.4,40.3 20,40.3 20,56
GND on Top Layer "Top Layer-No Net 1" (solid, pour order 1000): 18.2,40.7 15.7,40.7 15.7,41.4 1,41.4 1,56 19.7,56 19.7,44 17.7,44 17.7,42.6
GND on Top Layer "Top Layer-No Net 1" (solid, pour order 1006): 59.2,56 59.2,49.5 59.2,35.2 59.6,34.8 59.6,32.8 64.9,32.8 64.9,38.1 66.4,39.6 69.7,39.6 69.7,45.5 77.9,45.5 80.6,42.8 80.6,35.3 85.1,35.3 88,32.4 88,26.5 89.8,26.5 89.8,20.7 88,20.7 88,15 86.4,13.4 86.4,13.2 92.5,13.2 92.5,56
GND2 on Top Layer "Top Layer-No Net 1" (solid, pour order 1003): 16,1 92.5,1 92.5,12.9 56.3,12.9 55.3,12.3 46.2,12.3 36.9,21.6 36.5,21.6 36.5,17 36.9,16.6 40.3,16.6 40.3,13.8 40.9,13.2 40.9,11.2 39.4,11.2 38.7,10.5 36.1,10.5 35.1,11.5 26.9,11.5 24.9,9.5 16.4,9.5 15.4,10.5 15.1,10.8 13.3,10.8 13.3,13.2 12.1,13.2 12.1,19.7 13.6,21.2 23.6,21.2 23.6,17.1 30.4,17.1 30.4,18.4 31.2,18.4 31.2,21 32.6,22.4 35,22.4 35,25.2 33.9,25.2 32.8,26.3 8,26.4 1,26.4 1,1 8,1 8,9 15.9,9
GND2 on Bottom Layer "Top Layer-No Net 1" (solid, remove dead copper, pour order 1004): 8,1 92.5,1 92.5,12.7 46.5,12.7 36.9,22.3 35.5,22.3 35.5,25.6 8,25.6
GND on Bottom Layer "Top Layer-No Net 1" (solid, pour order 1005): 8,25.9 8,1 1,1 1,56 92.5,56 92.5,13 46.7,13 37.8,21.9 37.1,22.6 36.1,22.6 35.8,22.9 35.8,25.9 31.5,25.9

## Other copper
Top Layer:
  rectangle net GND: 80,42.74 82.4,45.06
  rectangle net GND: 81.6,40.74 84,43.06
  rectangle net GND: 82.4,35.3 86.7,39.7
  rectangle net +19V: 76.8,34.9 80,40.6
  rectangle net GND: 80.6,41.04 83,43.36
  region net +24V: 57.7,32.8 57.7,34.5 54.8,34.5 53.7,33.4 53.7,32.8
  region net GND: 32.5,52.3 26.8,52.3 26.8,43.9 32.5,43.9
  region net GND: 43.2,25.4 43.2,27.9 43.4,28.1 48.2,28.1 48.4,27.9 48.4,25.4
  region net GND: 44,37.3 46.1,37.3 46.1,35.4 46.6,34.9 46.6,28.9 43.7,28.9 43.7,35.2 44,35.5
  region net NetC27_1: 58.9,28.9 60.2,28.9 60.2,32.4 59,32.4 59,32.3 58.9,32.3
  region net NetD3_1: 48.4,25 48.4,22.5 48.2,22.3 43.4,22.3 43.2,22.5 43.2,25
  region net +24V: 25.8,51.9 20.3,51.9 20.3,43.5 25.8,43.5
  pour cut-out: 10.1,50.6 13.9,50.6 13.9,54.4 10.1,54.4
  pour cut-out: 8,51 8,43 16,43 15.9,43.1 15.9,51
  pour cut-out: 83,51 83,43 91,43 90.9,43.1 90.9,51
  pour cut-out: 83,9 83,1 91,1 90.9,1.1 90.9,9
  pour cut-out: 78.4,3.1 82.2,3.1 82.2,6.9 78.4,6.9
  pour cut-out: 8,9 8,1 16,1 15.9,1.1 15.9,9
  pour cut-out: 83.35,55.7 83.35,52.9 90.25,52.9 90.25,55.7
  text "TOP" at 84.1,53.8 h1.02
Bottom Layer:
  rectangle net GND: 26.8,44.3 30.9,52.3
  rectangle net GND: 79,31.1 83.7,34
  rectangle net GND: 82.5,34.9 86.1,40.4
  pour cut-out: 8,51 8,43 16,43 15.9,43.1 15.9,51
  pour cut-out: 83,51 83,43 91,43 90.9,43.1 90.9,51
  pour cut-out: 83,9 83,1 91,1 90.9,1.1 90.9,9
  pour cut-out: 8,9 8,1 16,1 15.9,1.1 15.9,9
  pour cut-out: 83.35,55.7 83.35,52.9 90.25,52.9 90.25,55.7
  text "BOTTOM" at 89.9,53.8 h1.02

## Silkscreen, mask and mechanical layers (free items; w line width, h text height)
Top Overlay:
  lines w0.2: 8,1 16,1 16,9 8,9 8,1 ; 8,43 8,51 16,51 16,43 8,43 ; 83,1 91,1 91,9 83,9 83,1 ; 83,43.7 83,51 91,51 91,43 83.7,43 83,43.7
  text "HeaterBoard rev. 1.1" at 60.5,53.6 h1.02
  text "24V" at 36.2,53.4 h1.5
  text "www.ultimaker.com/hb11" at 60.5,51.949 h1.02
  text "CdB/RT" at 60.503,50.173 h1.02
  text "19V 7A" at 80.6,30.3 h1.5
  text "BED" at 10.6,27.4 h1.5
  text "PT100" at 18.1,26.4 h1 r270
  text "switch" at 70.9,12.2 h1.5
  text "temp" at 45.6,8.5 h1.5 r90
Bottom Overlay:
  drawing of 22 lines, arcs and shapes, not listed
Mechanical 1:
  the board outline again, w0.2
  text ".Pcb_File_Name_No_Path" at 0.1,-1.7 h1.52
